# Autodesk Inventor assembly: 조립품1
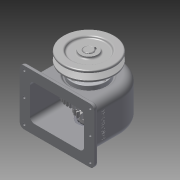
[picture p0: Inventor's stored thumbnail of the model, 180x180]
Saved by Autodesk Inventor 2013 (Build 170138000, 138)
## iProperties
Created: 2016-01
Part Number: 조립품1
Document SubType Name: Assembly
Designer: Administrator
Author: Administrator
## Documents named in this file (16)
- C:\Users\Administrator\Desktop\460105V1009\조립품1.iam
- C:\Users\Administrator\Desktop\460105V1009\1본체.ipt
- C:\Users\Administrator\Desktop\460105V1009\공용부품\V-벨트풀리.ipt
- C:\Users\Administrator\Desktop\460105V1009\공용부품\뒤커버.ipt
- C:\Users\Administrator\Desktop\460105V1009\공용부품\멈춤나사 - M4x10.ipt
- C:\Users\Administrator\Desktop\460105V1009\공용부품\베어링 6203.ipt
- C:\Users\Administrator\Desktop\460105V1009\공용부품\볼트 M3 x 8.ipt
- C:\Users\Administrator\Desktop\460105V1009\공용부품\볼트 M3 x 10.ipt
- C:\Users\Administrator\Desktop\460105V1009\공용부품\부시1.ipt
- C:\Users\Administrator\Desktop\460105V1009\공용부품\부시2.ipt
- C:\Users\Administrator\Desktop\460105V1009\공용부품\스퍼기어.ipt
- C:\Users\Administrator\Desktop\460105V1009\공용부품\앞커버.ipt
- C:\Users\Administrator\Desktop\460105V1009\공용부품\오일씰 28 40 8.ipt
- C:\Users\Administrator\Desktop\460105V1009\공용부품\축.ipt
- C:\Users\Administrator\Desktop\460105V1009\공용부품\키 - 5 x 5 x 18.ipt
- C:\Users\Administrator\Desktop\460105V1009\공용부품\키 - 6 x 6 x 22.ipt
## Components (10 placed, 4 different names)
1. 1본체:1
2. V-벨트풀리:1
3. ISO 4762 M3 x 10:1
4. ISO 4762 M3 x 10:2
5. ISO 4762 M3 x 10:3
6. ISO 4762 M3 x 10:4
7. ISO 4762 M3 x 8:1
8. ISO 4762 M3 x 8:2
9. ISO 4762 M3 x 8:3
10. ISO 4762 M3 x 8:4
